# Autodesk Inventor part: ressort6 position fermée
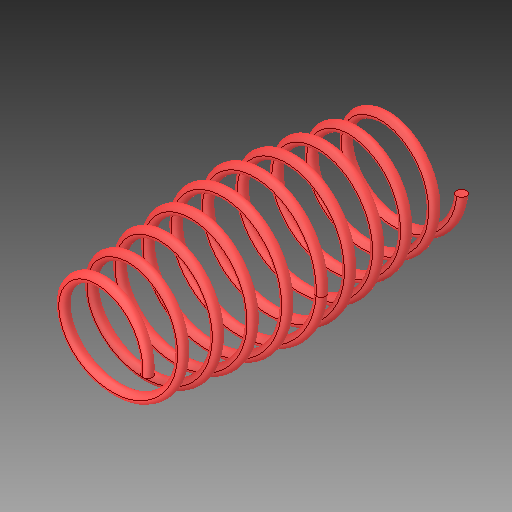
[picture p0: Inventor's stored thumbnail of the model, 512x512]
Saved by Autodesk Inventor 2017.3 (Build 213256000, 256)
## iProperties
Created: 2008-01
Part Number: ressort6 position fermée
Material: Générique
Document SubType Name: Modeling
Designer: ficho
Density: 1 g/cm^3
Appearance: Par défaut
Author: ficho
Sending System: SolidWorks 2009
Last Author: christophe
Last Saved: 2011-02-10
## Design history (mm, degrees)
feature "Balayage2"
node "Solide1"
